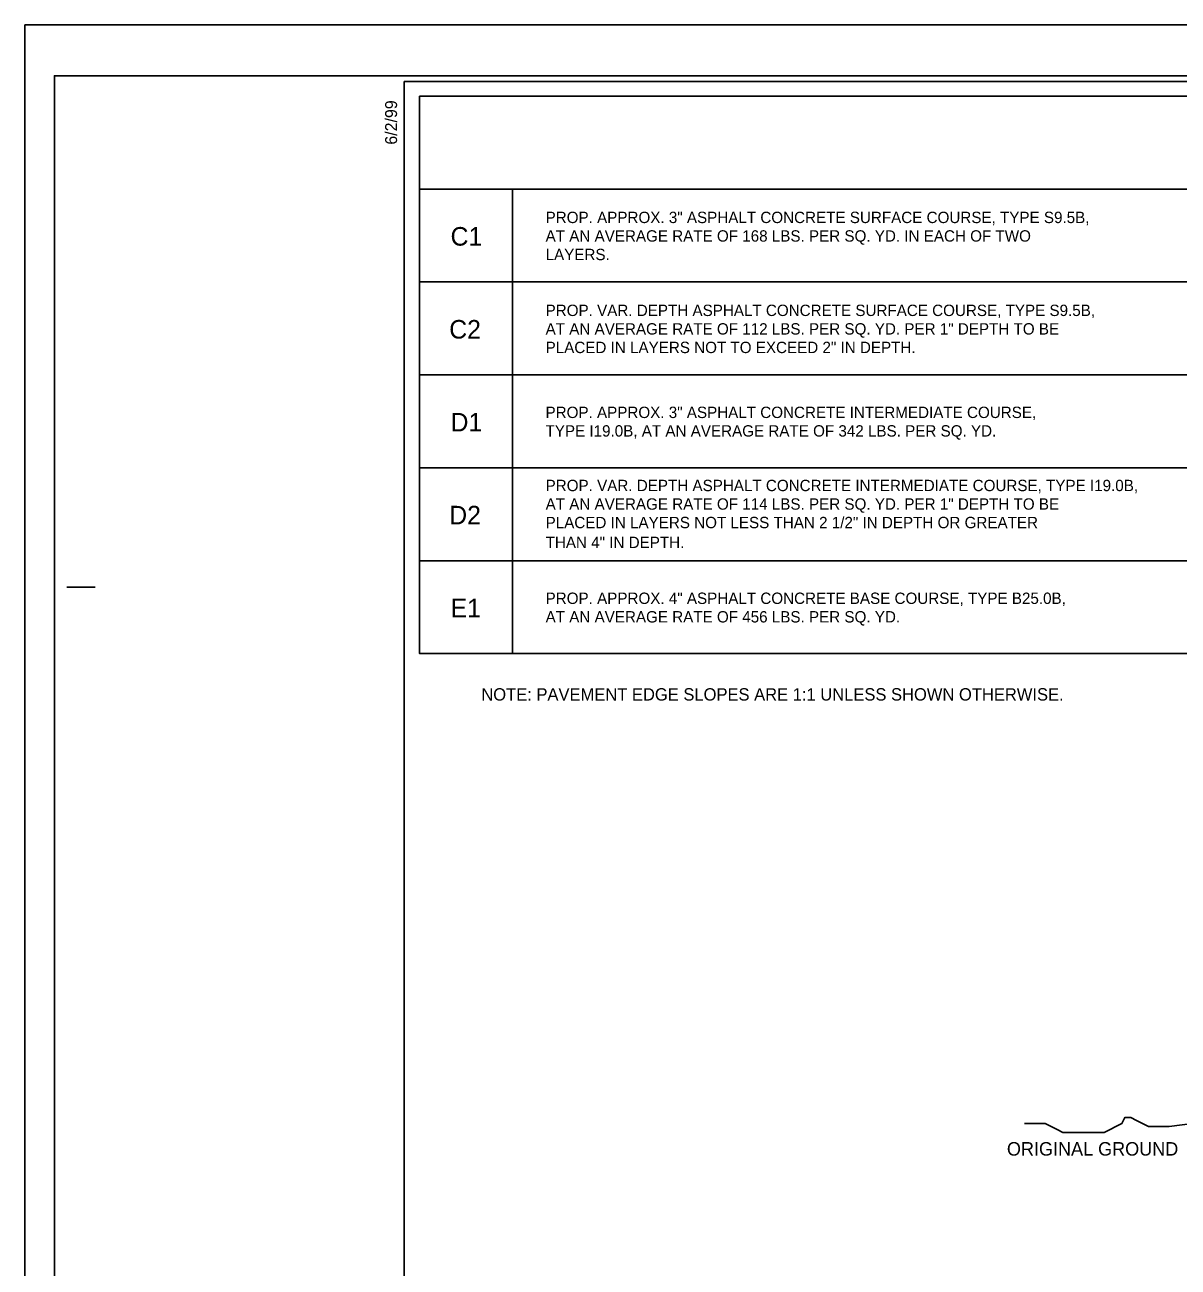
# Model space of a CAD drawing. Extents: x 693533 to 693723, y 486383 to 486493.
# Drawn here: x 693532.7 to 693583.4, y 486438.6 to 486493.3 of the extents above; entities that cross this region are included whole.
import ezdxf

# ---------------------------------------------------------------- set-up
doc = ezdxf.new("R2010")
doc.units = 0
for name, color, linetype in [('Old_Level_1', 7, 'Continuous'), ('Old_Level_19', 7, 'Continuous'), ('Old_Level_21', 7, 'Continuous'), ('Prop Pavement Schedule Description CELL', 7, 'Continuous'), ('Sheet Cutting Line CELL', 7, 'Continuous'), ('Sheet Plot Border Inside CELL', 7, 'Continuous'), ('Sheet Plot Border Outside CELL', 7, 'Continuous'), ('Sheet Typical CELL', 7, 'Continuous'), ('Typical Hinge Slope Arterial CELL', 7, 'Continuous'), ('Typical Slope Point Local CELL', 7, 'Continuous')]:
    doc.layers.add(name, color=color, linetype=linetype)

msp = doc.modelspace()

# ---------------------------------------------------------------- linework, layer by layer
at = {"layer": 'Old_Level_1'}
msp.add_line((693550.034, 486465.631), (693550.034, 486465.631), dxfattribs=at)
at = {"layer": 'Old_Level_19'}
msp.add_lwpolyline([(693550.034, 486490.177), (693630.033, 486490.177), (693630.033, 486486.086), (693550.034, 486486.086)], close=True, dxfattribs=at)
at = {"layer": 'Prop Pavement Schedule Description CELL'}
for points in [[(693554.124, 486481.994), (693550.034, 486481.994), (693550.034, 486486.086), (693590.034, 486486.086), (693590.034, 486481.994), (693554.124, 486481.994), (693554.124, 486486.086)], [(693554.124, 486477.902), (693550.034, 486477.902), (693550.034, 486481.994), (693590.034, 486481.994), (693590.034, 486477.902), (693554.124, 486477.902), (693554.124, 486481.994)], [(693554.124, 486473.813), (693550.034, 486473.813), (693550.034, 486477.903), (693590.034, 486477.903), (693590.034, 486473.813), (693554.124, 486473.813), (693554.124, 486477.903)], [(693554.124, 486469.721), (693550.034, 486469.721), (693550.034, 486473.813), (693590.034, 486473.813), (693590.034, 486469.721), (693554.124, 486469.721), (693554.124, 486473.813)], [(693554.124, 486465.631), (693550.034, 486465.631), (693550.034, 486469.722), (693590.034, 486469.722), (693590.034, 486465.631), (693554.124, 486465.631), (693554.124, 486469.722)]]:
    msp.add_lwpolyline(points, dxfattribs=at)
at = {"layer": 'Sheet Cutting Line CELL'}
for p, q in [((693701.059, 486493.314), (693532.659, 486493.314)), ((693532.659, 486493.314), (693532.659, 486383.314))]:
    msp.add_line(p, q, dxfattribs=at)
at = {"layer": 'Sheet Plot Border Inside CELL'}
msp.add_lwpolyline([(693700.609, 486491.069), (693533.959, 486491.069), (693533.959, 486385.559), (693700.609, 486385.559)], close=True, dxfattribs=at)
at = {"layer": 'Sheet Plot Border Outside CELL'}
msp.add_lwpolyline([(693701.059, 486493.314), (693532.659, 486493.314), (693532.659, 486383.314), (693701.059, 486383.314)], close=True, dxfattribs=at)
at = {"layer": 'Sheet Typical CELL'}
msp.add_line((693534.509, 486468.564), (693535.759, 486468.564), dxfattribs=at)
msp.add_lwpolyline([(693699.359, 486490.814), (693549.359, 486490.814), (693549.359, 486385.814), (693699.359, 486385.814)], close=True, dxfattribs=at)
at = {"layer": 'Typical Slope Point Local CELL'}
msp.add_lwpolyline([(693584.062, 486444.942), (693583.025, 486444.813), (693582.766, 486444.813), (693582.376, 486444.813), (693582.117, 486444.813), (693581.857, 486444.942), (693581.598, 486445.072), (693581.339, 486445.203), (693581.079, 486445.203), (693580.949, 486444.942), (693580.69, 486444.813), (693580.43, 486444.683), (693580.171, 486444.554), (693579.912, 486444.554), (693579.652, 486444.554), (693579.393, 486444.554), (693579.134, 486444.554), (693578.874, 486444.554), (693578.615, 486444.554), (693578.356, 486444.554), (693578.096, 486444.683), (693577.837, 486444.813), (693577.578, 486444.942), (693577.188, 486444.942), (693576.929, 486444.942), (693576.67, 486444.942)], dxfattribs=at)

# ---------------------------------------------------------------- texts
at = {"layer": 'Old_Level_21'}
msp.add_text('NOTE: PAVEMENT EDGE SLOPES ARE 1:1 UNLESS SHOWN OTHERWISE.', height=0.54417, dxfattribs=at).set_placement((693552.752, 486463.565))
at = {"layer": 'Prop Pavement Schedule Description CELL'}
for s, height, p in [('PROP. APPROX. 3" ASPHALT CONCRETE SURFACE COURSE, TYPE S9.5B, ', 0.5, (693555.583, 486484.586)), ('C1', 0.8167, (693551.398, 486483.594)), ('AT AN AVERAGE RATE OF 168 LBS. PER SQ. YD. IN EACH OF TWO ', 0.5, (693555.583, 486483.77)), ('LAYERS.', 0.5, (693555.583, 486482.954)), ('PROP. VAR. DEPTH ASPHALT CONCRETE SURFACE COURSE, TYPE S9.5B, ', 0.5, (693555.583, 486480.494)), ('C2', 0.8167, (693551.34, 486479.502)), ('AT AN AVERAGE RATE OF 112 LBS. PER SQ. YD. PER 1" DEPTH TO BE', 0.5, (693555.583, 486479.678)), ('PLACED IN LAYERS NOT TO EXCEED 2" IN DEPTH.', 0.5, (693555.583, 486478.862)), ('PROP. APPROX. 3" ASPHALT CONCRETE INTERMEDIATE COURSE,', 0.5, (693555.579, 486476.003)), ('D1', 0.8167, (693551.398, 486475.412)), ('TYPE I19.0B, AT AN AVERAGE RATE OF 342 LBS. PER SQ. YD.', 0.5, (693555.579, 486475.187)), ('PROP. VAR. DEPTH ASPHALT CONCRETE INTERMEDIATE COURSE, TYPE I19.0B, ', 0.5, (693555.583, 486472.784)), ('D2', 0.8167, (693551.34, 486471.321)), ('AT AN AVERAGE RATE OF 114 LBS. PER SQ. YD. PER 1" DEPTH TO BE', 0.5, (693555.583, 486471.968)), ('PLACED IN LAYERS NOT LESS THAN 2 1/2" IN DEPTH OR GREATER', 0.5, (693555.583, 486471.153)), ('THAN 4" IN DEPTH.', 0.5, (693555.583, 486470.278)), ('PROP. APPROX. 4" ASPHALT CONCRETE BASE COURSE, TYPE B25.0B,', 0.5, (693555.583, 486467.818)), ('E1', 0.8167, (693551.398, 486467.23)), ('AT AN AVERAGE RATE OF 456 LBS. PER SQ. YD.', 0.5, (693555.583, 486467.002))]:
    msp.add_text(s, height=height, dxfattribs=at).set_placement(p)
at = {"layer": 'Sheet Typical CELL'}
msp.add_text('6/2/99', height=0.525, rotation=90, dxfattribs=at).set_placement((693549.044, 486488.039))
at = {"layer": 'Typical Hinge Slope Arterial CELL'}
msp.add_text('ORIGINAL GROUND', height=0.59365, dxfattribs=at).set_placement((693575.89, 486443.531))

doc.saveas('drawing.dxf')
